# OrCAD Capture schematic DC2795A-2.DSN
size A
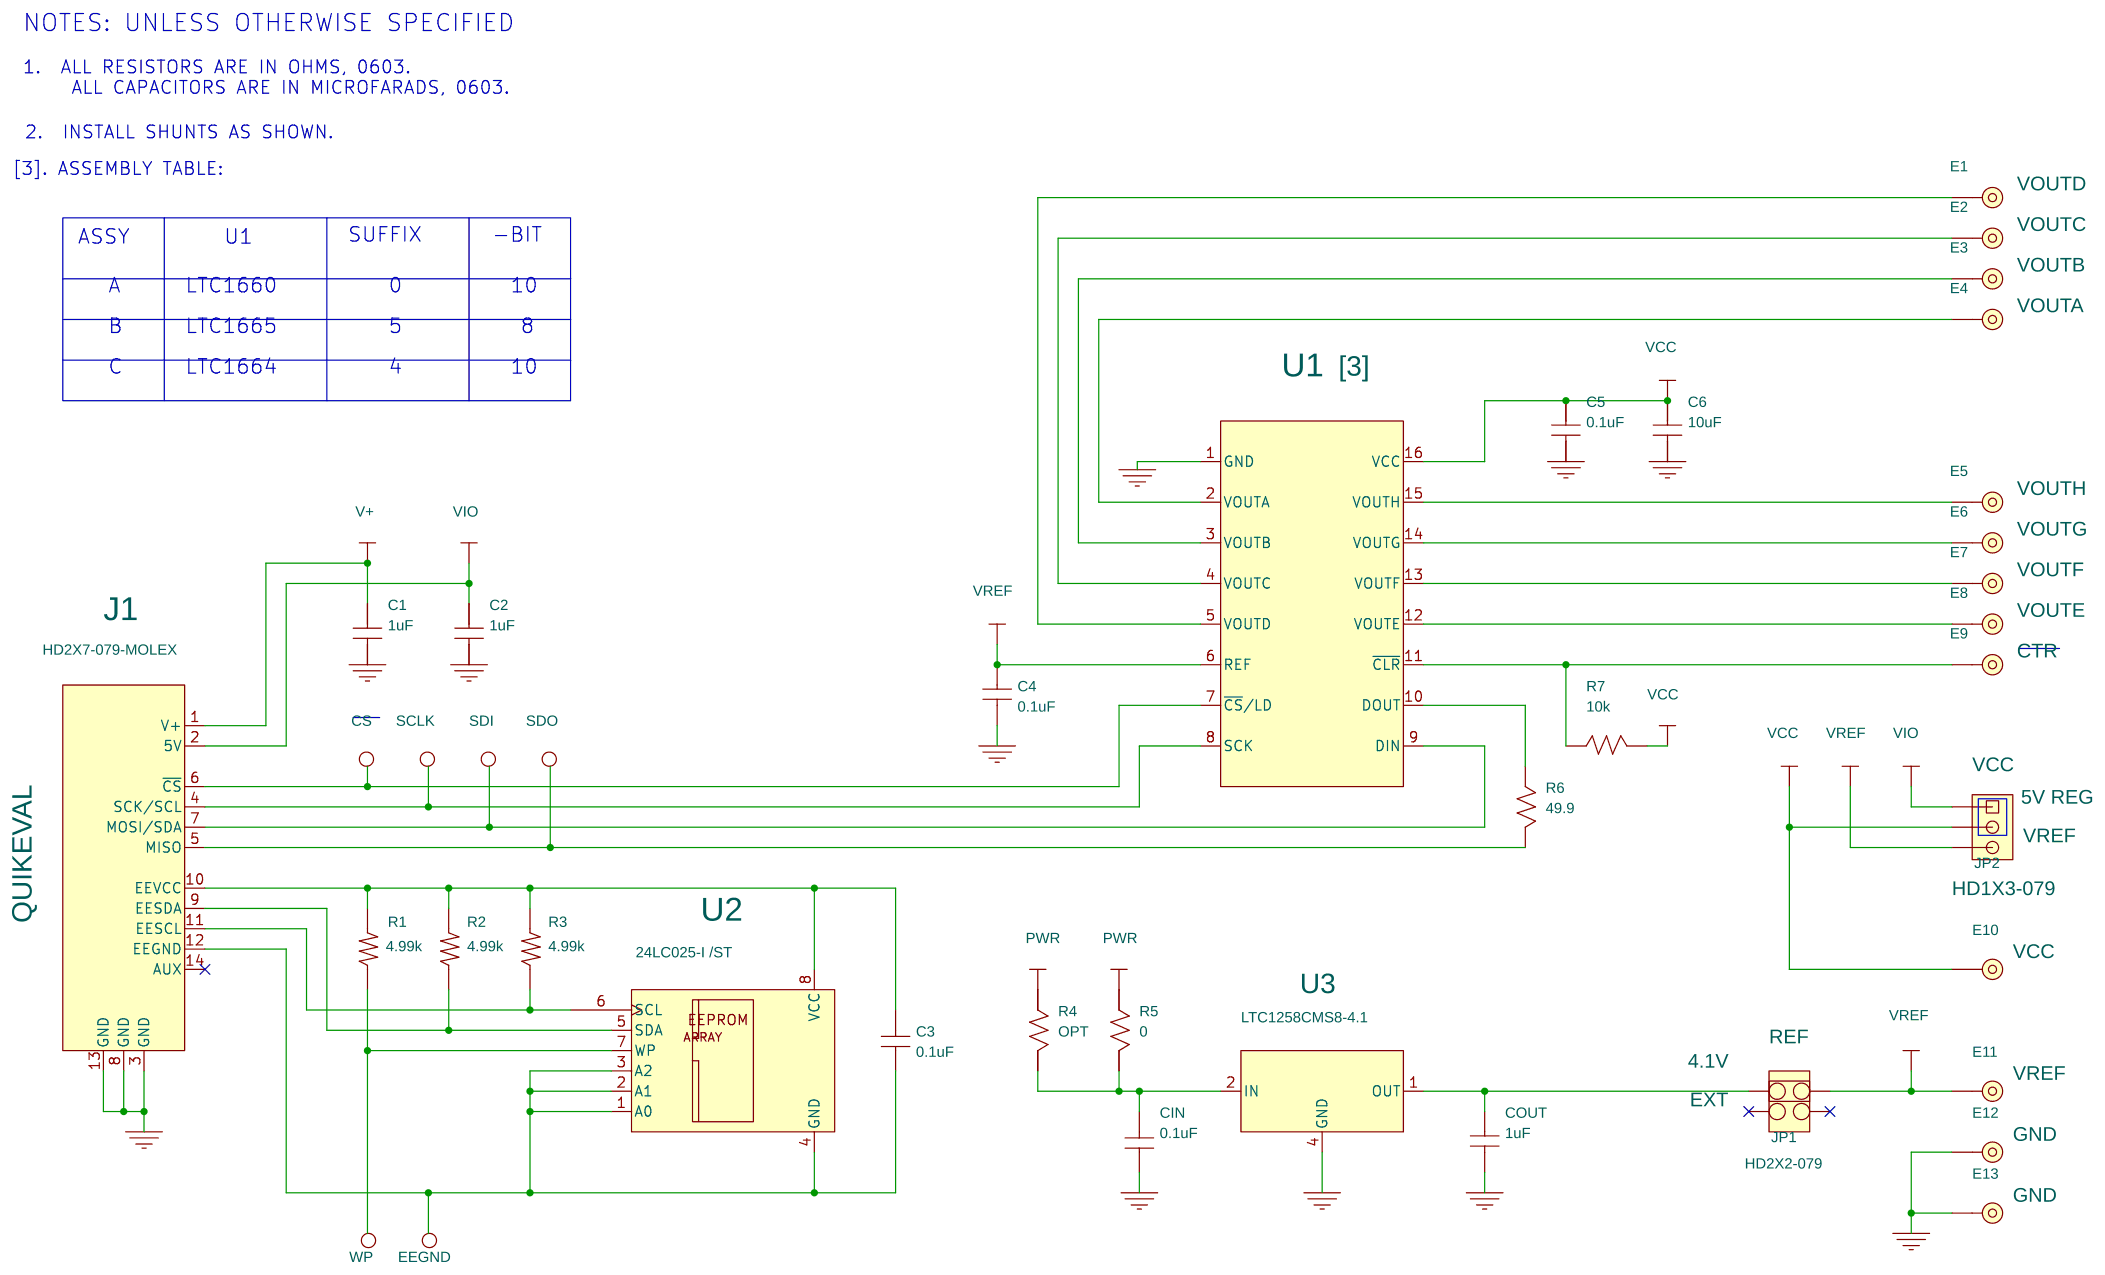
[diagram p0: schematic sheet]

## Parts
C1  1uF  [0603]
C2  1uF  [0603]
C3  0.1uF  [0603]
C4  0.1uF  [0603]
C5  0.1uF  [0603]
C6  10uF  [0603]
CIN  0.1uF  [0603]
COUT  1uF  [0603]
CS  PAD060-035  [PAD060-035]
E1  PAD120-064  [PAD120-064]
E2  PAD120-064  [PAD120-064]
E3  PAD120-064  [PAD120-064]
E4  PAD120-064  [PAD120-064]
E5  PAD120-064  [PAD120-064]
E6  PAD120-064  [PAD120-064]
E7  PAD120-064  [PAD120-064]
E8  PAD120-064  [PAD120-064]
E9  PAD120-064  [PAD120-064]
E10  PAD120-064  [PAD120-064]
E11  PAD120-064  [PAD120-064]
E12  PAD120-064  [PAD120-064]
E13  PAD120-064  [PAD120-064]
EEGND  PAD060-035  [PAD060-035]
J1  HD2X7-079-MOLEX  [HD2X7-079-MOLEX]
JP1  HD2X2-079  [HD2X2-079]
JP2  HD1X3-079  [HD1X3-079]
R1  4.99k  [0603]
R2  4.99k  [0603]
R3  4.99k  [0603]
R4  OPT  [0603]
R5  0  [0603]
R6  49.9  [0603]
R7  10k  [0603]
SCLK  PAD060-035  [PAD060-035]
SDI  PAD060-035  [PAD060-035]
SDO  PAD060-035  [PAD060-035]
U1  [3]  [SSOP16GN]
U2  24LC025-I /ST  [TSSOP8]
U3  LTC1258CMS8-4.1  [MS8]
WP  PAD060-035  [PAD060-035]

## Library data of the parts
C1-C6 CIN COUT = CAP-NP
CS EEGND SCLK SDI SDO WP = E-060-035
E1 = E-064_0: COMPFIXED: VOUTD
E2 = E-064_0: COMPFIXED: VOUTC
E3 = E-064_0: COMPFIXED: VOUTB
E4 = E-064_0: COMPFIXED: VOUTA
E5 = E-064_0: COMPFIXED: VOUTH
E6 = E-064_0: COMPFIXED: VOUTG
E7 = E-064_0: COMPFIXED: VOUTF
E8 = E-064_0: COMPFIXED: VOUTE
E9 = E-064_0: COMPFIXED: CTR
E10 = E-064_0: COMPFIXED: VCC
E11 = E-064_0: COMPFIXED: VREF
E12 E13 = E-064_0: COMPFIXED: GND
J1 = HD2X7-079-MOLEX: 1ST PART FIELD: QUIKEVAL
JP1 = HD2X2-079_0: 1ST PART FIELD: REF; 2ND PART FIELD: EXT; 3RD PART FIELD: 4.1V
JP2 = HD1X3: COMPFIXED: VCC; COMPGROUP: 5V REG; COMPKEY: VREF
R1-R3 = R
R4-R7 = R-SMALL
U1 = LTC1660IGN-SSOP16GN
U2 = 24LC025-I_ST
U3 = LTC1258CMS8-4.1-MS8

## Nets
GND: C1.2 C2.2 C4.2 C5.2 C6.2 CIN.1 COUT.2 E12.1(A) E13.1(A) J1.3(GND) J1.8(GND) J1.13(GND) U1.1(GND) U3.4(GND)
VCC: C5.1 C6.1 E10.1(A) JP2.2 R7.1 U1.16(VCC)
V+: C1.1 J1.1(V+) R4.2
VIO: C2.1 J1.2(5V) JP2.1 R5.2
VREF: C4.1 E11.1(A) JP1.2 JP2.3 U1.6(REF)
N16431226: COUT.1 JP1.1 U3.1(OUT)
N16726328: CS.1 J1.6(~{CS}) U1.7(~{CS}/LD)
N16726332: J1.4(SCK/SCL) SCLK.1 U1.8(SCK)
N16726336: J1.7(MOSI/SDA) SDI.1 U1.9(DIN)
N16726340: J1.5(MISO) R6.1 SDO.1
N16726384: C3.2 J1.10(EEVCC) R1.2 R2.2 R3.2 U2.8(VCC)
N16726424: J1.9(EESDA) R2.1 U2.5(SDA)
N16726432: J1.11(EESCL) R3.1 U2.6(SCL)
N16726488: C3.1 EEGND.1 J1.12(EEGND) U2.1(A0) U2.2(A1) U2.3(A2) U2.4(GND)
N16726524: R1.1 U2.7(WP) WP.1
N16730425: CIN.2 R4.1 R5.1 U3.2(IN)
N16735547: E7.1(A) U1.13(VOUTF)
N16735577: E8.1(A) U1.12(VOUTE)
N16754456: E9.1(A) R7.2 U1.11(~{CLR})
N16755230: E5.1(A) U1.15(VOUTH)
N16755246: E6.1(A) U1.14(VOUTG)
N16755350: E1.1(A) U1.5(VOUTD)
N16755366: E2.1(A) U1.4(VOUTC)
N16755394: E3.1(A) U1.3(VOUTB)
N16755410: E4.1(A) U1.2(VOUTA)
N16757955: R6.2 U1.10(DOUT)

Not connected (* = marked no-connect by the designer): J1 14(AUX)*; JP1 3* 4*

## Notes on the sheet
- NOTES: UNLESS OTHERWISE SPECIFIED
- 1.  ALL RESISTORS ARE IN OHMS, 0603.
       ALL CAPACITORS ARE IN MICROFARADS, 0603.
- 2.  INSTALL SHUNTS AS SHOWN.
- [3]. ASSEMBLY TABLE:
- ASSY
- U1
- SUFFIX
- -BIT
- A
- LTC1660
- 0
- 10
- B
- LTC1665
- 5
- 8
- C
- LTC1664
- 4
- 10
